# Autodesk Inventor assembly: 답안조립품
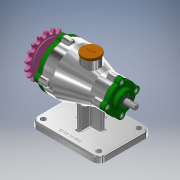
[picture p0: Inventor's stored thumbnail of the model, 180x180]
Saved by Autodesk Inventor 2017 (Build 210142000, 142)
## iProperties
Part Number: 답안조립품
Material: 일반
Document SubType Name: Assembly
Designer: 222
Author: 222
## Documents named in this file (15)
- C:\Users\222\Desktop\701206V1016\답안조립품.iam
- C:\Users\222\Desktop\701206V1016\개스킷 A.ipt
- C:\Users\222\Desktop\701206V1016\개스킷 B.ipt
- C:\Users\222\Desktop\701206V1016\뒤커버.ipt
- C:\Users\222\Desktop\701206V1016\마개.ipt
- C:\Users\222\Desktop\701206V1016\베어링 6200.ipt
- C:\Users\222\Desktop\701206V1016\베어링 6203.ipt
- C:\Users\222\Desktop\701206V1016\본체.ipt
- C:\Users\222\Desktop\701206V1016\볼트 M5.ipt
- C:\Users\222\Desktop\701206V1016\스프로킷.ipt
- C:\Users\222\Desktop\701206V1016\앞커버.ipt
- C:\Users\222\Desktop\701206V1016\오일 실 10 20 7.ipt
- C:\Users\222\Desktop\701206V1016\오일 실 17 30 8.ipt
- C:\Users\222\Desktop\701206V1016\축.ipt
- C:\Users\222\Desktop\701206V1016\키 4x4x14.ipt
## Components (2 placed, 2 different names)
1. 개스킷 A:1
2. 개스킷 B:1
